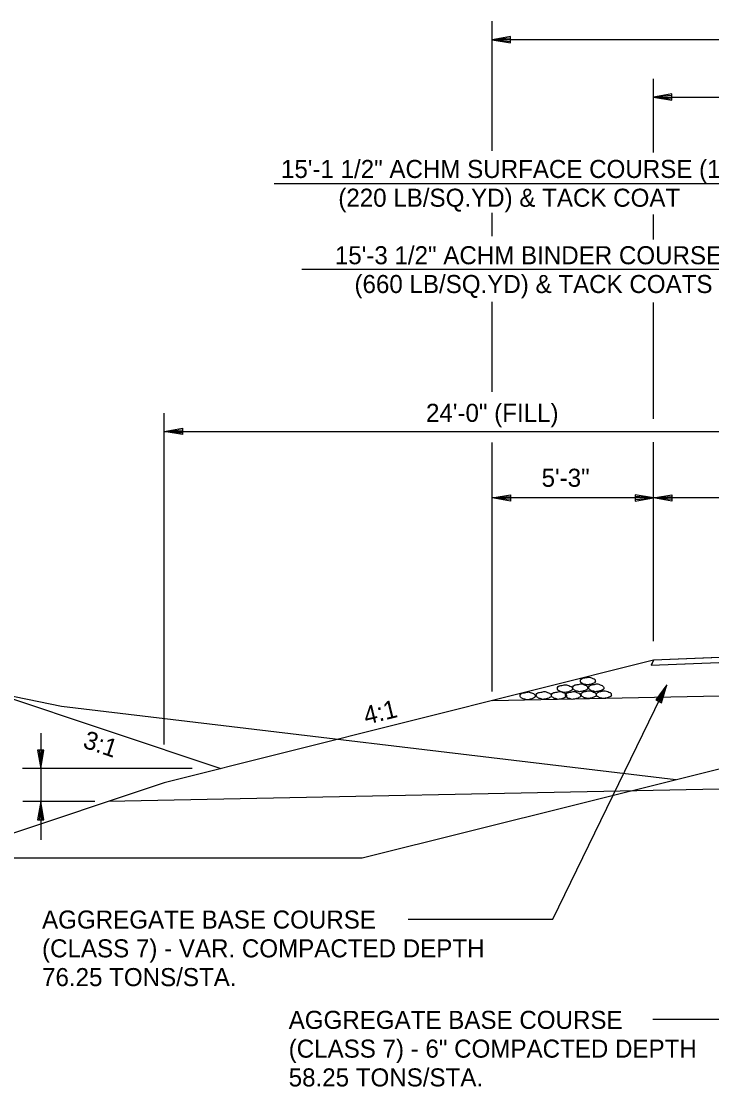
# Model space of a CAD drawing. Extents: x 1398565 to 1398920, y 1968324 to 1968581.
# Drawn here: x 1398801.5 to 1398824.08, y 1968387.88 to 1968422.68 of the extents above; entities that cross this region are included whole.
import ezdxf

# ---------------------------------------------------------------- set-up
doc = ezdxf.new("R2010")
doc.units = 0
for name, color, linetype in [('1', 7, 'Continuous'), ('10', 7, 'Continuous'), ('19', 7, 'Continuous'), ('42', 7, 'Continuous'), ('Default', 7, 'Continuous')]:
    doc.layers.add(name, color=color, linetype=linetype)

# ---------------------------------------------------------------- blocks, each defined once
blk = doc.blocks.new('ROCKS')
at = {"layer": '1'}
blk.add_spline([(0.013, 0.06), (0.053, 0.053), (0.107, 0.033), (0.133, 0.013), (0.133, -0.007), (0.12, -0.033), (0.107, -0.04), (0.073, -0.053), (0.033, -0.067), (0.013, -0.067), (-0.02, -0.06), (-0.06, -0.053), (-0.087, -0.047), (-0.113, -0.02), (-0.113, -0.007), (-0.107, 0.02), (-0.087, 0.033), (-0.067, 0.047), (-0.033, 0.053), (-0.02, 0.06), (0.013, 0.06)], degree=3, dxfattribs=at)
blk = doc.blocks.new('4TO1 ABC')
at = {"layer": '1', "xscale": 0.1312491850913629, "yscale": 0.1312491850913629, "rotation": 180}
for p in [(0.00175, -0.00875), (-0.016625, -0.023625), (0.018375, -0.023625), (0.051625, -0.025375), (-0.03325, -0.0385), (0, -0.0385), (0.034125, -0.04025), (0.06475, -0.04025), (0.098, -0.04025), (0.133, -0.041125)]:
    blk.add_blockref('ROCKS', p, dxfattribs=at)

msp = doc.modelspace()

# ---------------------------------------------------------------- linework, layer by layer
at = {"layer": '19'}
for p, q in [((1398816.893, 1968418.453), (1398816.893, 1968422.684)), ((1398817.493, 1968422.189), (1398816.893, 1968422.084)), ((1398843.176, 1968422.084), (1398816.893, 1968422.084)), ((1398816.893, 1968422.084), (1398817.493, 1968421.979)), ((1398817.493, 1968422.134), (1398817.053, 1968422.099)), ((1398817.053, 1968422.069), (1398817.493, 1968422.029)), ((1398817.493, 1968421.979), (1398817.493, 1968422.189)), ((1398822.176, 1968418.397), (1398822.176, 1968420.809)), ((1398822.776, 1968420.314), (1398822.176, 1968420.209)), ((1398822.176, 1968420.209), (1398862.176, 1968420.209)), ((1398822.176, 1968420.209), (1398822.776, 1968420.104)), ((1398822.776, 1968420.259), (1398822.336, 1968420.224)), ((1398822.336, 1968420.194), (1398822.776, 1968420.154)), ((1398822.776, 1968420.104), (1398822.776, 1968420.314)), ((1398809.771, 1968417.387), (1398843.176, 1968417.387)), ((1398816.893, 1968415.665), (1398816.893, 1968416.425)), ((1398822.176, 1968415.552), (1398822.176, 1968416.369)), ((1398810.671, 1968414.589), (1398843.176, 1968414.589)), ((1398816.893, 1968410.574), (1398816.893, 1968413.524)), ((1398822.176, 1968409.693), (1398822.176, 1968413.496)), ((1398806.176, 1968399.062), (1398806.176, 1968409.885)), ((1398806.176, 1968409.285), (1398806.776, 1968409.39)), ((1398806.776, 1968409.39), (1398806.776, 1968409.18)), ((1398806.176, 1968409.285), (1398830.176, 1968409.285)), ((1398806.776, 1968409.18), (1398806.176, 1968409.285)), ((1398806.336, 1968409.3), (1398806.776, 1968409.335)), ((1398806.776, 1968409.23), (1398806.336, 1968409.27)), ((1398816.893, 1968400.793), (1398816.893, 1968408.926)), ((1398822.176, 1968402.429), (1398822.176, 1968408.94)), ((1398816.893, 1968407.113), (1398817.493, 1968407.218)), ((1398830.181, 1968407.113), (1398816.893, 1968407.113)), ((1398817.493, 1968407.008), (1398816.893, 1968407.113)), ((1398817.053, 1968407.128), (1398817.493, 1968407.163)), ((1398817.493, 1968407.058), (1398817.053, 1968407.098)), ((1398817.493, 1968407.218), (1398817.493, 1968407.008)), ((1398821.576, 1968407.218), (1398821.576, 1968407.008)), ((1398822.176, 1968407.113), (1398821.576, 1968407.218)), ((1398822.016, 1968407.128), (1398821.576, 1968407.163)), ((1398821.576, 1968407.008), (1398822.176, 1968407.113)), ((1398821.576, 1968407.058), (1398822.016, 1968407.098)), ((1398822.176, 1968407.113), (1398822.776, 1968407.218)), ((1398822.776, 1968407.008), (1398822.176, 1968407.113)), ((1398822.336, 1968407.128), (1398822.776, 1968407.163)), ((1398822.776, 1968407.058), (1398822.336, 1968407.098)), ((1398822.776, 1968407.218), (1398822.776, 1968407.008)), ((1398822.176, 1968401.81), (1398806.176, 1968397.808)), ((1398828.176, 1968401.884), (1398822.091, 1968401.64)), ((1398822.176, 1968401.81), (1398822.091, 1968401.64)), ((1398828.176, 1968402.05), (1398822.176, 1968401.81)), ((1398800.557, 1968400.762), (1398808.028, 1968398.272)), ((1398842.176, 1968400.995), (1398816.893, 1968400.489)), ((1398818.882, 1968393.347), (1398822.61, 1968401.005)), ((1398822.61, 1968401.005), (1398822.247, 1968400.516)), ((1398822.528, 1968400.868), (1398822.295, 1968400.495)), ((1398822.39, 1968400.446), (1398822.553, 1968400.855)), ((1398822.434, 1968400.424), (1398822.61, 1968401.005)), ((1398822.247, 1968400.516), (1398822.434, 1968400.424)), ((1398802.137, 1968399.43), (1398802.137, 1968398.154)), ((1398802.242, 1968398.872), (1398802.032, 1968398.872)), ((1398802.032, 1968398.872), (1398802.137, 1968398.272)), ((1398802.087, 1968398.872), (1398802.122, 1968398.432)), ((1398802.137, 1968398.272), (1398802.242, 1968398.872)), ((1398802.152, 1968398.432), (1398802.192, 1968398.872)), ((1398802.137, 1968398.154), (1398802.137, 1968395.948)), ((1398843.176, 1968397.975), (1398804.345, 1968397.198)), ((1398806.176, 1968397.808), (1398798.814, 1968395.354)), ((1398802.137, 1968397.198), (1398802.032, 1968396.598)), ((1398802.242, 1968396.598), (1398802.137, 1968397.198)), ((1398802.122, 1968397.038), (1398802.087, 1968396.598)), ((1398802.192, 1968396.598), (1398802.152, 1968397.038)), ((1398802.032, 1968396.598), (1398802.242, 1968396.598)), ((1398814.154, 1968393.347), (1398818.882, 1968393.347)), ((1398822.153, 1968390.087), (1398825.682, 1968390.087))]:
    msp.add_line(p, q, dxfattribs=at)
msp.add_lwpolyline([(1398822.093, 1968401.645), (1398828.176, 1968401.884), (1398842.176, 1968402.164), (1398856.176, 1968401.884), (1398862.261, 1968401.64), (1398862.176, 1968401.81), (1398856.176, 1968402.05), (1398842.176, 1968402.33), (1398828.176, 1968402.05), (1398822.176, 1968401.81)], close=True, dxfattribs=at)
at = {"layer": '42'}
for points in [[(1398822.902, 1968397.908), (1398802.82, 1968400.302), (1398800.522, 1968400.764), (1398796.614, 1968400.956), (1398791.017, 1968401.495), (1398768.256, 1968402.089)], [(1398766.153, 1968395.354), (1398812.649, 1968395.354), (1398837.176, 1968401.464), (1398843.176, 1968401.704)]]:
    msp.add_lwpolyline(points, dxfattribs=at)
at = {"layer": 'Default'}
for p, q in [((1398807.086, 1968398.272), (1398801.542, 1968398.272)), ((1398803.908, 1968397.198), (1398801.556, 1968397.198))]:
    msp.add_line(p, q, dxfattribs=at)

# ---------------------------------------------------------------- block references
at = {"layer": '19', "xscale": 14.999970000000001, "yscale": -14.999970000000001, "rotation": 180}
msp.add_blockref('4TO1 ABC', (1398820.033, 1968401.257), dxfattribs=at)

# ---------------------------------------------------------------- texts
at = {"layer": '10'}
for s, height, rotation, p in [('24\'-0" (FILL)', 0.59001, 360, (1398814.734, 1968409.598)), ('5\'-3"', 0.59, 360, (1398818.514, 1968407.477)), ('4:1', 0.59, 13.7364, (1398812.774, 1968399.7)), ('3:1', 0.59, 341.5224, (1398803.482, 1968398.967))]:
    msp.add_text(s, height=height, rotation=rotation, dxfattribs=at).set_placement(p)
at = {"layer": '19'}
for s, p in [('AGGREGATE BASE COURSE', (1398802.18, 1968393.043)), ('(CLASS 7) - VAR. COMPACTED DEPTH', (1398802.18, 1968392.103)), ('76.25 TONS/STA.', (1398802.18, 1968391.163)), ('AGGREGATE BASE COURSE', (1398810.244, 1968389.766)), ('(CLASS 7) - 6" COMPACTED DEPTH', (1398810.244, 1968388.826)), ('58.25 TONS/STA.', (1398810.244, 1968387.886))]:
    msp.add_text(s, height=0.59001, rotation=360, dxfattribs=at).set_placement(p)
at = {"layer": '42'}
for s, p in [('15\'-1 1/2" ACHM SURFACE COURSE (1/2")', (1398809.992, 1968417.566)), ('(220 LB/SQ.YD) & TACK COAT', (1398811.866, 1968416.626)), ('15\'-3 1/2" ACHM BINDER COURSE (1")', (1398811.754, 1968414.747)), ('(660 LB/SQ.YD) & TACK COATS', (1398812.395, 1968413.807))]:
    msp.add_text(s, height=0.59001, rotation=360, dxfattribs=at).set_placement(p)

doc.saveas('drawing.dxf')
